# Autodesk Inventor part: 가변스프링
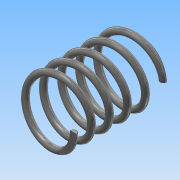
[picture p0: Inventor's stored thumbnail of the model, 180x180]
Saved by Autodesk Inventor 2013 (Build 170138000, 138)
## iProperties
Created: 2017-12
Part Number: 가변스프링
Material: 스테인리스강
Document SubType Name: Modeling
Designer: Administrator
Mass: 7.08197 g
Surface Area: 17.7615 cm^2
Volume: 0.876482 cm^3
Density: 8.08 g/cm^3
Author: Administrator
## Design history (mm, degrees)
sketch "스케치1"
  geometry: L1 (0, 0)-(9, 0); L2 (9, 0)-(9, -28.5); L3 (9, -28.5)-(0, -28.5); L4 (0, -28.5)-(0, 0); C1 r 1 at (9, 0)
  constraints: 8 end point, 2 parallel, 1 centre point, 1 coincident, 1 horizontal, 1 perpendicular
  dimensions: "d0" = 28.5 distance of L3.end L1.start (derived); "d1" = 18 diameter of L2 L4; "d2" = 2 diameter of C1
feature "코일1" sketch "스케치1" pitch "d3" = 10; turns "d5" = 5; dims "d4" = 28.5 (= d0), "d6" = 0, angle "d7" = 90 deg, angle "d8" = 90 deg, "d9" = 0, "d10" = 0
sketch "스케치2"
  geometry: L1 (0, 20)-(-28.5, 20); L2 (-28.5, 20)-(-28.5, -20); L3 (-28.5, -20)-(0, -20); L4 (0, -20)-(0, 20); 4 further points
  constraints: 8 end point, 2 coincident, 2 midpoint, 2 parallel, 1 horizontal, 1 perpendicular
  dimensions: "d11" = 40 distance of L1.end L2.end
extrude "돌출1" sketch "스케치2" stored distance "d13" = 30; taper "d14" = 0 deg
node "솔리드1"
